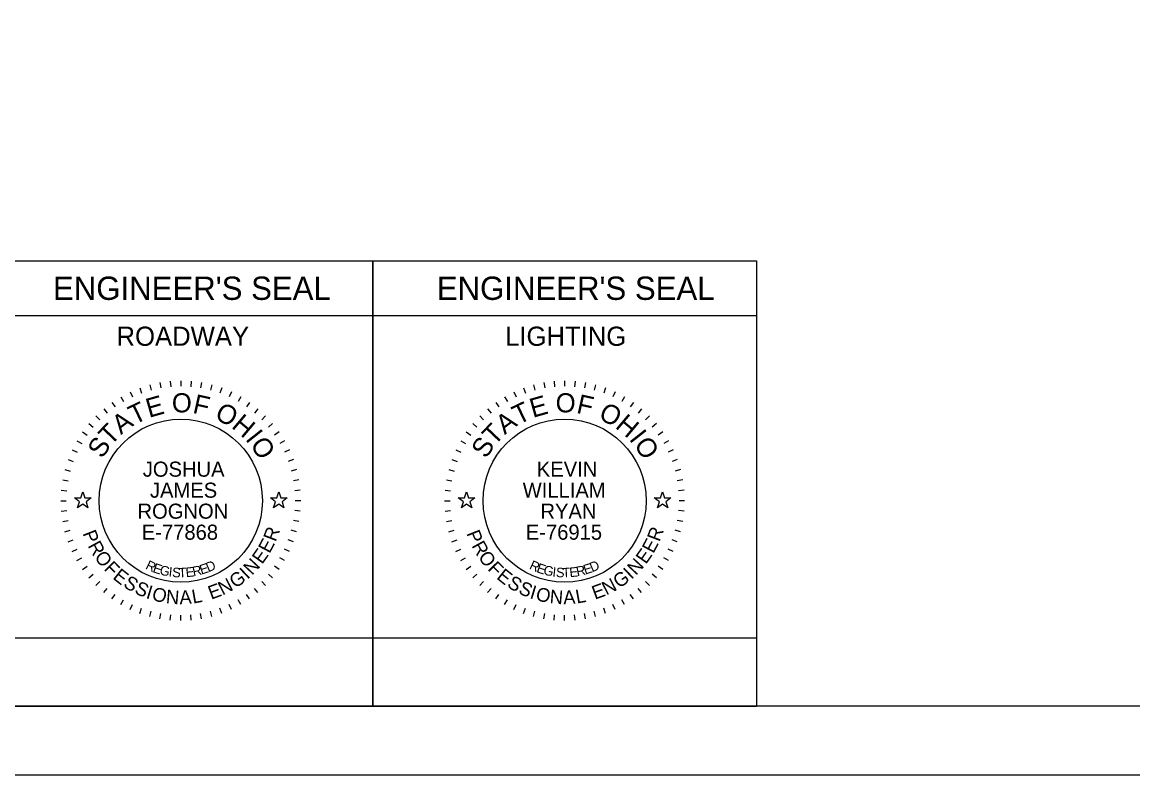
# Model space of a CAD drawing. Extents: x 0 to 36.9, y 0 to 22.
# Drawn here: x 23.84 to 31.95, y 0 to 5.49 of the extents above; entities that cross this region are included whole.
import ezdxf

# ---------------------------------------------------------------- set-up
doc = ezdxf.new("R2010")
doc.units = 0
for name, color, linetype in [('SH_Border', 7, 'Continuous'), ('SH_Cut_Line', 7, 'Continuous'), ('SH_Data', 7, 'Continuous'), ('SH_Seal', 7, 'Continuous')]:
    doc.layers.add(name, color=color, linetype=linetype)

msp = doc.modelspace()

# ---------------------------------------------------------------- linework, layer by layer
at = {"layer": 'SH_Border'}
msp.add_lwpolyline([(1.5, 21.5), (33.5, 21.5), (33.5, 0.5), (1.5, 0.5)], close=True, dxfattribs=at)
at = {"layer": 'SH_Cut_Line'}
msp.add_lwpolyline([(0, 0), (34, 0), (34, 22), (0, 22)], close=True, dxfattribs=at)
at = {"layer": 'SH_Data'}
for p, q in [((23.6, 3.75), (26.4, 3.75)), ((26.4, 3.75), (26.4, 0.5)), ((26.4, 0.5), (26.4, 3.75)), ((26.4, 3.75), (29.2, 3.75)), ((29.2, 3.75), (29.2, 0.5)), ((23.6, 3.35), (26.4, 3.35)), ((26.4, 3.35), (29.2, 3.35)), ((23.6, 0.5), (26.4, 0.5)), ((26.4, 0.5), (29.2, 0.5))]:
    msp.add_line(p, q, dxfattribs=at)
for points in [[(23.6, 0.5), (23.6, 1), (26.4, 1), (26.4, 0.5)], [(26.4, 0.5), (26.4, 1), (29.2, 1), (29.2, 0.5)]]:
    msp.add_lwpolyline(points, close=True, dxfattribs=at)
at = {"layer": 'SH_Seal'}
for p, q in [((24.7735, 2.8452), (24.7839, 2.8065)), ((24.8481, 2.8617), (24.855, 2.8223)), ((24.9237, 2.8717), (24.9272, 2.8318)), ((25, 2.875), (25, 2.835)), ((25.0763, 2.8717), (25.0728, 2.8318)), ((25.1519, 2.8617), (25.145, 2.8223)), ((25.2265, 2.8452), (25.2161, 2.8065)), ((27.5735, 2.8452), (27.5839, 2.8065)), ((27.6481, 2.8617), (27.655, 2.8223)), ((27.7237, 2.8717), (27.7272, 2.8318)), ((27.8, 2.875), (27.8, 2.835)), ((27.8763, 2.8717), (27.8728, 2.8318)), ((27.9519, 2.8617), (27.945, 2.8223)), ((28.0265, 2.8452), (28.0161, 2.8065)), ((24.5625, 2.7578), (24.5825, 2.7231)), ((24.6302, 2.793), (24.6471, 2.7568)), ((24.7007, 2.8222), (24.7144, 2.7846)), ((25.2993, 2.8222), (25.2856, 2.7846)), ((25.3698, 2.793), (25.3529, 2.7568)), ((25.4375, 2.7578), (25.4175, 2.7231)), ((27.3625, 2.7578), (27.3825, 2.7231)), ((27.4302, 2.793), (27.4471, 2.7568)), ((27.5007, 2.8222), (27.5144, 2.7846)), ((28.0993, 2.8222), (28.0856, 2.7846)), ((28.1698, 2.793), (28.1529, 2.7568)), ((28.2375, 2.7578), (28.2175, 2.7231)), ((24.4981, 2.7168), (24.5211, 2.684)), ((25.5019, 2.7168), (25.4789, 2.684)), ((27.2981, 2.7168), (27.3211, 2.684)), ((28.3019, 2.7168), (28.2789, 2.684)), ((24.3813, 2.6187), (24.4096, 2.5904)), ((24.4376, 2.6703), (24.4633, 2.6396)), ((25.5624, 2.6703), (25.5367, 2.6396)), ((25.6187, 2.6187), (25.5904, 2.5904)), ((27.1813, 2.6187), (27.2096, 2.5904)), ((27.2376, 2.6703), (27.2633, 2.6396)), ((28.3624, 2.6703), (28.3367, 2.6396)), ((28.4187, 2.6187), (28.3904, 2.5904)), ((24.3297, 2.5624), (24.3604, 2.5367)), ((25.6703, 2.5624), (25.6396, 2.5367)), ((27.1297, 2.5624), (27.1604, 2.5367)), ((28.4703, 2.5624), (28.4396, 2.5367)), ((24.2422, 2.4375), (24.2769, 2.4175)), ((24.2832, 2.5019), (24.316, 2.4789)), ((25.7168, 2.5019), (25.684, 2.4789)), ((25.7578, 2.4375), (25.7231, 2.4175)), ((27.0422, 2.4375), (27.0769, 2.4175)), ((27.0832, 2.5019), (27.116, 2.4789)), ((28.5168, 2.5019), (28.484, 2.4789)), ((28.5578, 2.4375), (28.5231, 2.4175)), ((24.207, 2.3698), (24.2432, 2.3529)), ((25.793, 2.3698), (25.7568, 2.3529)), ((27.007, 2.3698), (27.0432, 2.3529)), ((28.593, 2.3698), (28.5568, 2.3529)), ((24.1778, 2.2993), (24.2154, 2.2856)), ((25.8222, 2.2993), (25.7846, 2.2856)), ((26.9778, 2.2993), (27.0154, 2.2856)), ((28.6222, 2.2993), (28.5846, 2.2856)), ((24.1548, 2.2265), (24.1935, 2.2161)), ((25.8452, 2.2265), (25.8065, 2.2161)), ((26.9548, 2.2265), (26.9935, 2.2161)), ((28.6452, 2.2265), (28.6065, 2.2161)), ((24.1383, 2.1519), (24.1777, 2.145)), ((25.8617, 2.1519), (25.8223, 2.145)), ((26.9383, 2.1519), (26.9777, 2.145)), ((28.6617, 2.1519), (28.6223, 2.145)), ((24.1283, 2.0763), (24.1682, 2.0728)), ((25.8717, 2.0763), (25.8318, 2.0728)), ((26.9283, 2.0763), (26.9682, 2.0728)), ((28.6717, 2.0763), (28.6318, 2.0728)), ((24.125, 2), (24.165, 2)), ((25.875, 2), (25.835, 2)), ((26.925, 2), (26.965, 2)), ((28.675, 2), (28.635, 2)), ((24.1283, 1.9237), (24.1682, 1.9272)), ((25.8717, 1.9237), (25.8318, 1.9272)), ((26.9283, 1.9237), (26.9682, 1.9272)), ((28.6717, 1.9237), (28.6318, 1.9272)), ((24.1383, 1.8481), (24.1777, 1.855)), ((24.1548, 1.7735), (24.1935, 1.7839)), ((25.8452, 1.7735), (25.8065, 1.7839)), ((25.8617, 1.8481), (25.8223, 1.855)), ((26.9383, 1.8481), (26.9777, 1.855)), ((26.9548, 1.7735), (26.9935, 1.7839)), ((28.6452, 1.7735), (28.6065, 1.7839)), ((28.6617, 1.8481), (28.6223, 1.855)), ((24.1778, 1.7007), (24.2154, 1.7144)), ((25.8222, 1.7007), (25.7846, 1.7144)), ((26.9778, 1.7007), (27.0154, 1.7144)), ((28.6222, 1.7007), (28.5846, 1.7144)), ((24.207, 1.6302), (24.2432, 1.6471)), ((25.793, 1.6302), (25.7568, 1.6471)), ((27.007, 1.6302), (27.0432, 1.6471)), ((28.593, 1.6302), (28.5568, 1.6471)), ((24.2422, 1.5625), (24.2769, 1.5825)), ((25.7578, 1.5625), (25.7231, 1.5825)), ((27.0422, 1.5625), (27.0769, 1.5825)), ((28.5578, 1.5625), (28.5231, 1.5825)), ((24.2832, 1.4981), (24.316, 1.5211)), ((24.3297, 1.4376), (24.3604, 1.4633)), ((25.6703, 1.4376), (25.6396, 1.4633)), ((25.7168, 1.4981), (25.684, 1.5211)), ((27.0832, 1.4981), (27.116, 1.5211)), ((27.1297, 1.4376), (27.1604, 1.4633)), ((28.4703, 1.4376), (28.4396, 1.4633)), ((28.5168, 1.4981), (28.484, 1.5211)), ((24.3813, 1.3813), (24.4096, 1.4096)), ((25.6187, 1.3813), (25.5904, 1.4096)), ((27.1813, 1.3813), (27.2096, 1.4096)), ((28.4187, 1.3813), (28.3904, 1.4096)), ((24.4376, 1.3297), (24.4633, 1.3604)), ((24.4981, 1.2832), (24.5211, 1.316)), ((25.5019, 1.2832), (25.4789, 1.316)), ((25.5624, 1.3297), (25.5367, 1.3604)), ((27.2376, 1.3297), (27.2633, 1.3604)), ((27.2981, 1.2832), (27.3211, 1.316)), ((28.3019, 1.2832), (28.2789, 1.316)), ((28.3624, 1.3297), (28.3367, 1.3604)), ((24.5625, 1.2422), (24.5825, 1.2769)), ((24.6302, 1.207), (24.6471, 1.2432)), ((25.3698, 1.207), (25.3529, 1.2432)), ((25.4375, 1.2422), (25.4175, 1.2769)), ((27.3625, 1.2422), (27.3825, 1.2769)), ((27.4302, 1.207), (27.4471, 1.2432)), ((28.1698, 1.207), (28.1529, 1.2432)), ((28.2375, 1.2422), (28.2175, 1.2769)), ((24.7007, 1.1778), (24.7144, 1.2154)), ((24.7735, 1.1548), (24.7839, 1.1935)), ((24.8481, 1.1383), (24.855, 1.1777)), ((24.9237, 1.1283), (24.9272, 1.1682)), ((25, 1.125), (25, 1.165)), ((25.0763, 1.1283), (25.0728, 1.1682)), ((25.1519, 1.1383), (25.145, 1.1777)), ((25.2265, 1.1548), (25.2161, 1.1935)), ((25.2993, 1.1778), (25.2856, 1.2154)), ((27.5007, 1.1778), (27.5144, 1.2154)), ((27.5735, 1.1548), (27.5839, 1.1935)), ((27.6481, 1.1383), (27.655, 1.1777)), ((27.7237, 1.1283), (27.7272, 1.1682)), ((27.8, 1.125), (27.8, 1.165)), ((27.8763, 1.1283), (27.8728, 1.1682)), ((27.9519, 1.1383), (27.945, 1.1777)), ((28.0265, 1.1548), (28.0161, 1.1935)), ((28.0993, 1.1778), (28.0856, 1.2154))]:
    msp.add_line(p, q, dxfattribs=at)
for points in [[(24.2236, 2.02), (24.2705, 2.02), (24.285, 2.0645), (24.2995, 2.02), (24.3464, 2.02), (24.3085, 1.9924), (24.323, 1.9478), (24.285, 1.9754), (24.247, 1.9478), (24.2615, 1.9924)], [(25.6536, 2.02), (25.7005, 2.02), (25.715, 2.0645), (25.7295, 2.02), (25.7764, 2.02), (25.7385, 1.9924), (25.753, 1.9478), (25.715, 1.9754), (25.677, 1.9478), (25.6915, 1.9924)], [(27.0236, 2.02), (27.0705, 2.02), (27.085, 2.0645), (27.0995, 2.02), (27.1464, 2.02), (27.1085, 1.9924), (27.123, 1.9478), (27.085, 1.9754), (27.047, 1.9478), (27.0615, 1.9924)], [(28.4536, 2.02), (28.5005, 2.02), (28.515, 2.0645), (28.5295, 2.02), (28.5764, 2.02), (28.5385, 1.9924), (28.553, 1.9478), (28.515, 1.9754), (28.477, 1.9478), (28.4915, 1.9924)]]:
    msp.add_lwpolyline(points, close=True, dxfattribs=at)
for centre in [(25, 2), (27.8, 2)]:
    msp.add_circle(centre, 0.595, dxfattribs=at)

# ---------------------------------------------------------------- texts
at = {"layer": 'SH_Data'}
for s, height, p in [("ENGINEER'S SEAL", 0.17, (24.0676, 3.465)), ("ENGINEER'S SEAL", 0.17, (26.8676, 3.465)), ('ROADWAY', 0.14, (24.5311, 3.13)), ('LIGHTING', 0.14, (27.366, 3.13))]:
    msp.add_text(s, height=height, dxfattribs=at).set_placement(p)
at = {"layer": 'SH_Seal'}
for s, height, rotation, p in [('E', 0.14, 15.75706, (24.7684, 2.6038)), ('O', 0.14, 359.78119, (24.9347, 2.6443)), ('F', 0.14, 347.43619, (25.0811, 2.6417)), ('E', 0.14, 15.75706, (27.5684, 2.6038)), ('O', 0.14, 359.78119, (27.7347, 2.6443)), ('F', 0.14, 347.43619, (27.8811, 2.6417)), ('T', 0.14, 25.71674, (24.6616, 2.5518)), ('O', 0.14, 332.25863, (25.2398, 2.6015)), ('T', 0.14, 25.71674, (27.4616, 2.5518)), ('O', 0.14, 332.25863, (28.0398, 2.6015)), ('A', 0.14, 36.47472, (24.5634, 2.4781)), ('H', 0.14, 319.91363, (25.3632, 2.5361)), ('A', 0.14, 36.47472, (27.3634, 2.4781)), ('H', 0.14, 319.91363, (28.1632, 2.5361)), ('T', 0.14, 46.4344, (24.4883, 2.3964)), ('I', 0.14, 308.36695, (25.4665, 2.4483)), ('T', 0.14, 46.4344, (27.2883, 2.3964)), ('I', 0.14, 308.36695, (28.2665, 2.4483)), ('S', 0.14, 57.19238, (24.4281, 2.3014)), ('O', 0.14, 303.14906, (25.5021, 2.4089)), ('S', 0.14, 57.19238, (27.2281, 2.3014)), ('O', 0.14, 303.14906, (28.3021, 2.4089)), ('P', 0.1, 291.49398, (24.2823, 1.7621)), ('R', 0.1, 69.23216, (25.6919, 1.6954)), ('P', 0.1, 291.49398, (27.0823, 1.7621)), ('R', 0.1, 69.23216, (28.4919, 1.6954)), ('R', 0.1, 298.73106, (24.319, 1.6717)), ('E', 0.1, 61.99508, (25.6476, 1.6098)), ('R', 0.1, 298.73106, (27.119, 1.6717)), ('E', 0.1, 61.99508, (28.4476, 1.6098)), ('O', 0.1, 306.46664, (24.3655, 1.5883)), ('E', 0.1, 54.75801, (25.5933, 1.5314)), ('O', 0.1, 306.46664, (27.1655, 1.5883)), ('E', 0.1, 54.75801, (28.3933, 1.5314)), ('F', 0.1, 314.7068, (24.4343, 1.4983)), ('R', 0.07, 334.48695, (24.7375, 1.5051)), ('E', 0.07, 341.03996, (24.7906, 1.4801)), ('E', 0.07, 17.68363, (25.1498, 1.4602)), ('D', 0.07, 23.30524, (25.201, 1.477)), ('N', 0.1, 47.02243, (25.5202, 1.4508)), ('F', 0.1, 314.7068, (27.2343, 1.4983)), ('R', 0.07, 334.48695, (27.5375, 1.5051)), ('E', 0.07, 341.03996, (27.5906, 1.4801)), ('E', 0.07, 17.68363, (27.9498, 1.4602)), ('D', 0.07, 23.30524, (28.001, 1.477)), ('N', 0.1, 47.02243, (28.3202, 1.4508)), ('E', 0.1, 321.43929, (24.4978, 1.4348)), ('G', 0.07, 347.47515, (24.8414, 1.4618)), ('I', 0.07, 353.78581, (24.9091, 1.4468)), ('S', 0.07, 356.89262, (24.9358, 1.4429)), ('T', 0.07, 3.00609, (24.9857, 1.4387)), ('E', 0.07, 6.01169, (25.0389, 1.4412)), ('R', 0.07, 11.91844, (25.0925, 1.4474)), ('G', 0.1, 35.04687, (25.3981, 1.357)), ('I', 0.1, 43.28703, (25.4868, 1.4214)), ('E', 0.1, 321.43929, (27.2978, 1.4348)), ('G', 0.07, 347.47515, (27.6414, 1.4618)), ('I', 0.07, 353.78581, (27.7091, 1.4468)), ('S', 0.07, 356.89262, (27.7358, 1.4429)), ('T', 0.07, 3.00609, (27.7857, 1.4387)), ('E', 0.07, 6.01169, (27.8389, 1.4412)), ('R', 0.07, 11.91844, (27.8925, 1.4474)), ('G', 0.1, 35.04687, (28.1981, 1.357)), ('I', 0.1, 43.28703, (28.2868, 1.4214)), ('S', 0.1, 328.67637, (24.5743, 1.3752)), ('S', 0.1, 335.91345, (24.6564, 1.3266)), ('I', 0.1, 343.15053, (24.7406, 1.2897)), ('E', 0.1, 20.07421, (25.2212, 1.277)), ('N', 0.1, 27.31129, (25.3045, 1.3075)), ('S', 0.1, 328.67637, (27.3743, 1.3752)), ('S', 0.1, 335.91345, (27.4564, 1.3266)), ('I', 0.1, 343.15053, (27.5406, 1.2897)), ('E', 0.1, 20.07421, (28.0212, 1.277)), ('N', 0.1, 27.31129, (28.1045, 1.3075)), ('O', 0.1, 346.88592, (24.7839, 1.2751)), ('N', 0.1, 355.12608, (24.8888, 1.2517)), ('A', 0.1, 2.86166, (24.9923, 1.2437)), ('L', 0.1, 10.09874, (25.0894, 1.249)), ('O', 0.1, 346.88592, (27.5839, 1.2751)), ('N', 0.1, 355.12608, (27.6888, 1.2517)), ('A', 0.1, 2.86166, (27.7923, 1.2437)), ('L', 0.1, 10.09874, (27.8894, 1.249))]:
    msp.add_text(s, height=height, rotation=rotation, dxfattribs=at).set_placement(p)
for s, p in [('JOSHUA', (24.7228, 2.1749)), ('KEVIN', (27.5975, 2.1749)), ('JAMES', (24.775, 2.0216)), ('WILLIAM', (27.4946, 2.0216)), ('ROGNON', (24.6843, 1.8684)), ('RYAN', (27.6241, 1.8684)), ('E-77868', (24.7157, 1.7151)), ('E-76915', (27.5173, 1.7151))]:
    msp.add_text(s, height=0.11, dxfattribs=at).set_placement(p)

doc.saveas('drawing.dxf')
